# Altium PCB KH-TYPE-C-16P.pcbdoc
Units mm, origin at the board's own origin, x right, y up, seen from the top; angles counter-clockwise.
Board outline 23.04 x 20.85 mm, 2 copper layers (Top Layer, Bottom Layer), stack 0 mm thick; 1 components, 0 nets, 20 pads, 0 vias.
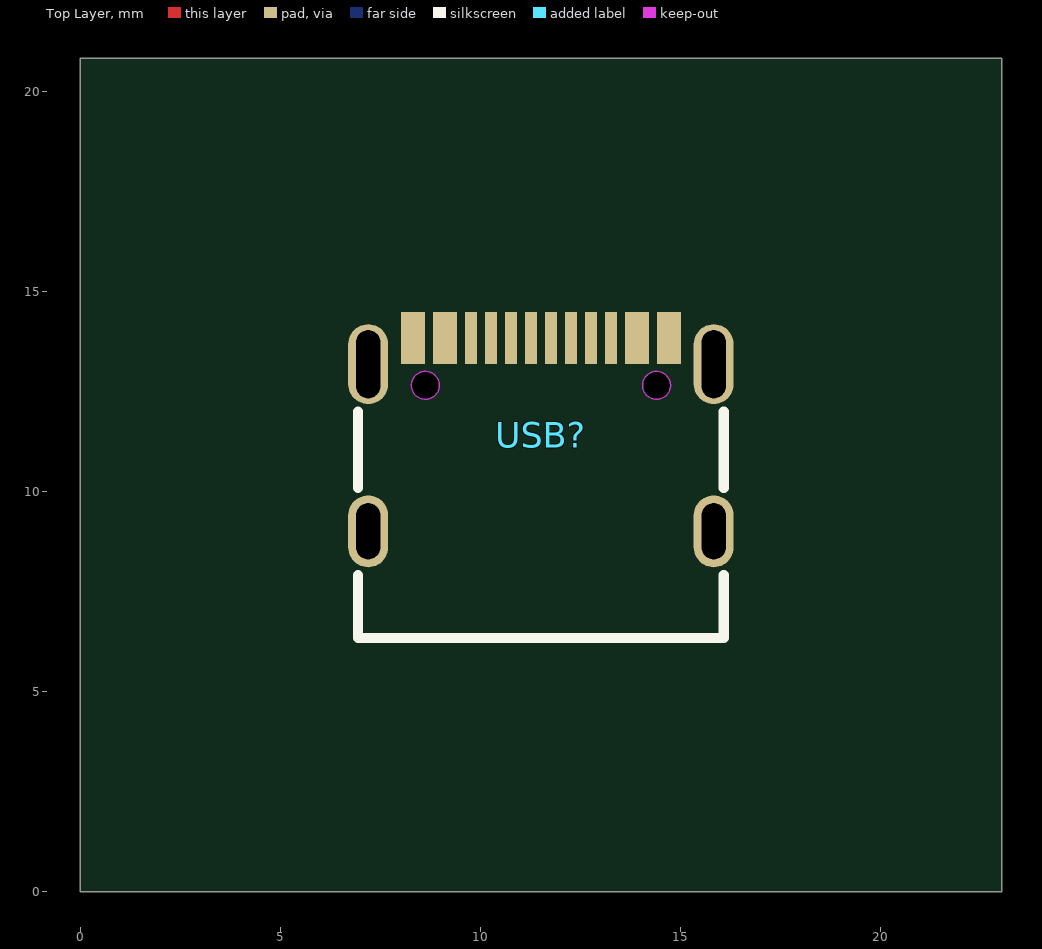
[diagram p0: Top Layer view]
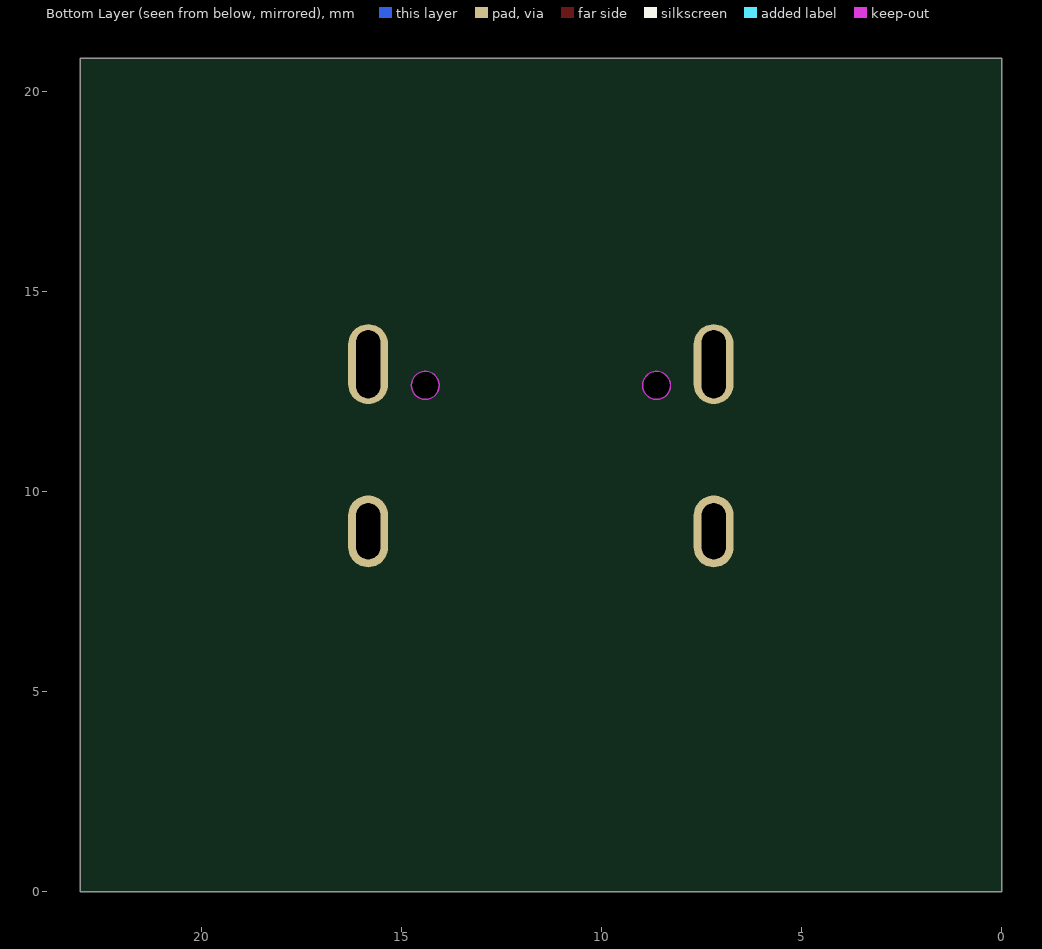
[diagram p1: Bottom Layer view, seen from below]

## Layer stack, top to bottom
Top Layer: signal copper (thickness not stored)
Bottom Layer: signal copper (thickness not stored)

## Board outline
23.04,0 0,0 0,20.845 23.04,20.845

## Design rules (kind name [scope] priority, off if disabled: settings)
PasteMaskExpansion "Paste Mask Expansion" [All] p1: expansion=0
SolderMaskExpansion "Solder Mask Expansion" [IsVia] p1: expansion=-25.4 istentingtop=TRUE
SolderMaskExpansion "Solder Mask Expansion" [All] p2: expansion=0.051 istentingtop=FALSE

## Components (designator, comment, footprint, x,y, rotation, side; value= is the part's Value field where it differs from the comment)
USB? "KH-TYPE-C-16P" USB-C-SMD_KH-TYPE-C-16P 11.52,11.43 r0 top

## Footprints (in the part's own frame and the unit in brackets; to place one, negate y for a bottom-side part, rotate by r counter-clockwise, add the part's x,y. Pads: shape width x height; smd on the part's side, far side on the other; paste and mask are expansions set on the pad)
USB-C-SMD_KH-TYPE-C-16P [mm]
  oval 1x2 hole 0.6 slot 1.7 at 90 deg: 1(-4.32,1.765) 2(4.32,1.765)
  oval 1x1.8 hole 0.6 slot 1.4 at 90 deg: 3(-4.32,-2.415) 4(4.32,-2.415)
  rect 0.3x1.3 smd paste-100 mask+0.05: A1(-3.35,2.415) A4(-2.55,2.415) A5(-1.25,2.415) A6(-0.25,2.415) A7(0.25,2.415) A8(1.25,2.415) A9(2.55,2.415) A12(3.35,2.415) B1(3.05,2.415) B4(2.25,2.415) B5(1.75,2.415) B6(0.75,2.415) B7(-0.75,2.415) B8(-1.75,2.415) B9(-2.25,2.415) B12(-3.05,2.415)
  Board Outline Layer circle w0.003: c-2.89,1.235 r0.35
  Board Outline Layer circle w0.003: c2.89,1.235 r0.35
  Board Outline Layer region: -2.54,1.235 -2.575,1.083 -2.672,0.961 -2.812,0.894 -2.968,0.894 -3.108,0.961 -3.205,1.083 -3.24,1.235 -3.24,1.235 -3.205,1.387 -3.108,1.509 -2.968,1.576 -2.812,1.576 -2.672,1.509 -2.575,1.387 -2.54,1.235
  Board Outline Layer region: -2.54,1.235 -2.549,1.157 -2.575,1.083 -2.616,1.017 -2.672,0.961 -2.738,0.92 -2.812,0.894 -2.89,0.885 -2.968,0.894 -3.042,0.92 -3.108,0.961 -3.164,1.017 -3.205,1.083 -3.231,1.157 -3.24,1.235 -3.231,1.313 -3.205,1.387 -3.164,1.453 -3.108,1.509 -3.042,1.55 -2.968,1.576 -2.89,1.585 -2.812,1.576 -2.738,1.55 -2.672,1.509 -2.616,1.453 -2.575,1.387 -2.549,1.313
  Board Outline Layer region: 3.24,1.235 3.205,1.083 3.108,0.961 2.968,0.894 2.812,0.894 2.672,0.961 2.575,1.083 2.54,1.235 2.54,1.235 2.575,1.387 2.672,1.509 2.812,1.576 2.968,1.576 3.108,1.509 3.205,1.387 3.24,1.235
  Board Outline Layer region: 3.24,1.235 3.231,1.157 3.205,1.083 3.164,1.017 3.108,0.961 3.042,0.92 2.968,0.894 2.89,0.885 2.812,0.894 2.738,0.92 2.672,0.961 2.616,1.017 2.575,1.083 2.549,1.157 2.54,1.235 2.549,1.313 2.575,1.387 2.616,1.453 2.672,1.509 2.738,1.55 2.812,1.576 2.89,1.585 2.968,1.576 3.042,1.55 3.108,1.509 3.164,1.453 3.205,1.387 3.231,1.313
  Multi-Layer board cut-out: -2.54,1.235 -2.575,1.083 -2.672,0.961 -2.812,0.894 -2.968,0.894 -3.108,0.961 -3.205,1.083 -3.24,1.235 -3.24,1.235 -3.205,1.387 -3.108,1.509 -2.968,1.576 -2.812,1.576 -2.672,1.509 -2.575,1.387 -2.54,1.235
  Multi-Layer board cut-out: 3.24,1.235 3.205,1.083 3.108,0.961 2.968,0.894 2.812,0.894 2.672,0.961 2.575,1.083 2.54,1.235 2.54,1.235 2.575,1.387 2.672,1.509 2.812,1.576 2.968,1.576 3.108,1.509 3.205,1.387 3.24,1.235
  silkscreen extent -4.57,-5.08 4.57,0.57

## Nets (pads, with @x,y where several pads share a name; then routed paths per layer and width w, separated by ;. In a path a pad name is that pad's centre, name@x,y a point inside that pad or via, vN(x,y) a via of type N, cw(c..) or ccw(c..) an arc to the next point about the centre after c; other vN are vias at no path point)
pads on no net: USB?.1 USB?.2 USB?.3 USB?.4 USB?.A1 USB?.A4 USB?.A5 USB?.A6 USB?.A7 USB?.A8 USB?.A9 USB?.A12 USB?.B1 USB?.B4 USB?.B5 USB?.B6 USB?.B7 USB?.B8 USB?.B9 USB?.B12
